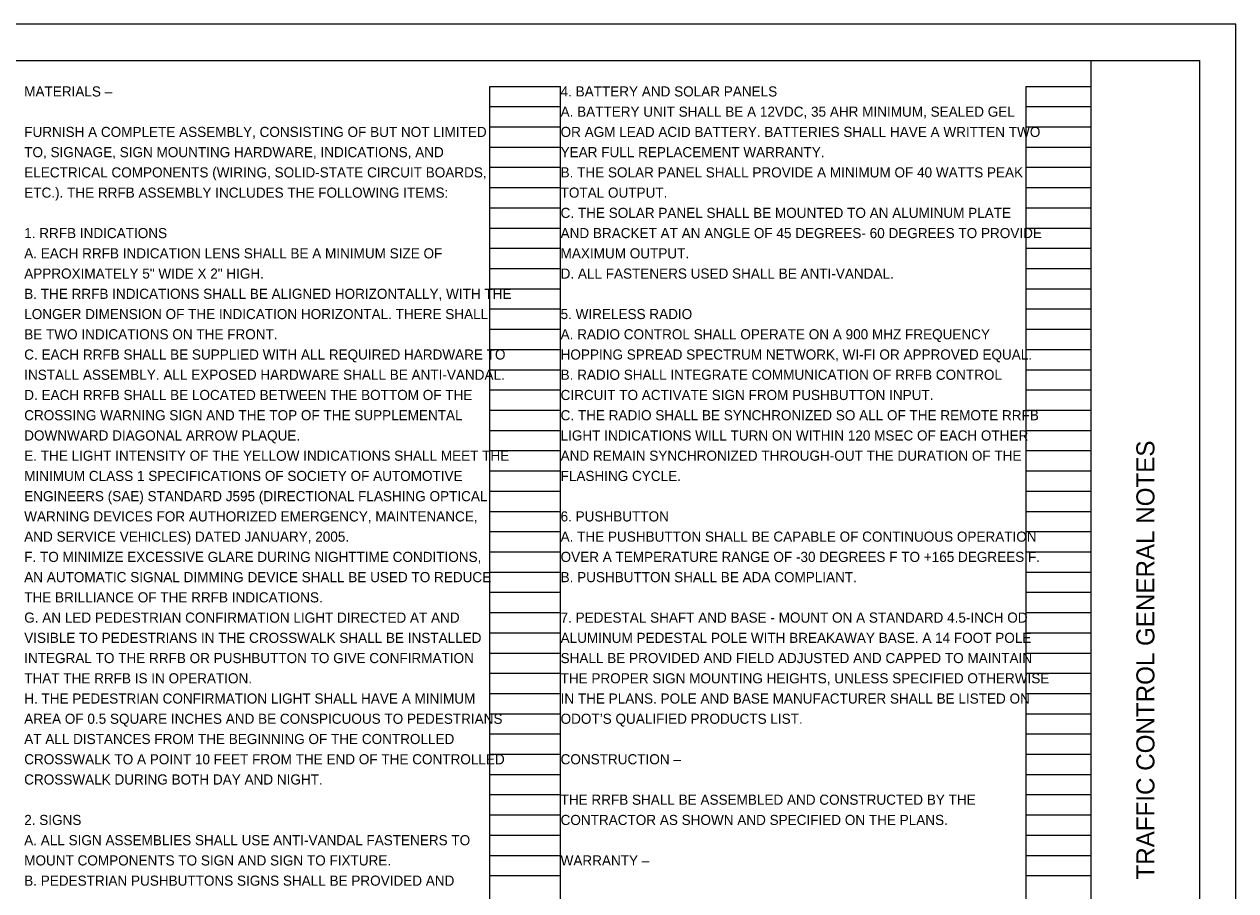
# Model space of a CAD drawing. Extents: x 0 to 34, y 0 to 22.
# Drawn here: x 17.24 to 34, y 10.01 to 22 of the extents above; entities that cross this region are included whole.
import ezdxf

# ---------------------------------------------------------------- set-up
doc = ezdxf.new("R2010")
doc.units = 0
for name, color, linetype in [('SH_Border', 7, 'Continuous'), ('SH_Cut_Line', 7, 'Continuous'), ('SH_Data', 7, 'Continuous'), ('SH_Text', 7, 'Continuous')]:
    doc.layers.add(name, color=color, linetype=linetype)

msp = doc.modelspace()

# ---------------------------------------------------------------- linework, layer by layer
at = {"layer": 'SH_Border'}
msp.add_line((32, 0.5), (32, 21.5), dxfattribs=at)
msp.add_lwpolyline([(1.5, 21.5), (33.5, 21.5), (33.5, 0.5), (1.5, 0.5)], close=True, dxfattribs=at)
at = {"layer": 'SH_Cut_Line'}
msp.add_lwpolyline([(0, 0), (34, 0), (34, 22), (0, 22)], close=True, dxfattribs=at)
at = {"layer": 'SH_Data'}
for p, q in [((23.68, 0.98), (23.68, 21.14)), ((23.68, 21.14), (24.66, 21.14)), ((24.66, 0.98), (24.66, 21.14)), ((31.1, 0.98), (31.1, 21.14)), ((31.1, 21.14), (32, 21.14)), ((32, 0.98), (32, 21.14)), ((23.68, 20.86), (24.66, 20.86)), ((31.1, 20.86), (32, 20.86)), ((23.68, 20.58), (24.66, 20.58)), ((31.1, 20.58), (32, 20.58)), ((23.68, 20.3), (24.66, 20.3)), ((31.1, 20.3), (32, 20.3)), ((23.68, 20.02), (24.66, 20.02)), ((31.1, 20.02), (32, 20.02)), ((23.68, 19.74), (24.66, 19.74)), ((31.1, 19.74), (32, 19.74)), ((23.68, 19.46), (24.66, 19.46)), ((31.1, 19.46), (32, 19.46)), ((23.68, 19.18), (24.66, 19.18)), ((31.1, 19.18), (32, 19.18)), ((23.68, 18.9), (24.66, 18.9)), ((31.1, 18.9), (32, 18.9)), ((23.68, 18.62), (24.66, 18.62)), ((31.1, 18.62), (32, 18.62)), ((23.68, 18.34), (24.66, 18.34)), ((31.1, 18.34), (32, 18.34)), ((23.68, 18.06), (24.66, 18.06)), ((31.1, 18.06), (32, 18.06)), ((23.68, 17.78), (24.66, 17.78)), ((31.1, 17.78), (32, 17.78)), ((23.68, 17.5), (24.66, 17.5)), ((31.1, 17.5), (32, 17.5)), ((23.68, 17.22), (24.66, 17.22)), ((31.1, 17.22), (32, 17.22)), ((23.68, 16.94), (24.66, 16.94)), ((31.1, 16.94), (32, 16.94)), ((23.68, 16.66), (24.66, 16.66)), ((31.1, 16.66), (32, 16.66)), ((23.68, 16.38), (24.66, 16.38)), ((31.1, 16.38), (32, 16.38)), ((23.68, 16.1), (24.66, 16.1)), ((31.1, 16.1), (32, 16.1)), ((23.68, 15.82), (24.66, 15.82)), ((31.1, 15.82), (32, 15.82)), ((23.68, 15.54), (24.66, 15.54)), ((31.1, 15.54), (32, 15.54)), ((23.68, 15.26), (24.66, 15.26)), ((31.1, 15.26), (32, 15.26)), ((23.68, 14.98), (24.66, 14.98)), ((31.1, 14.98), (32, 14.98)), ((23.68, 14.7), (24.66, 14.7)), ((31.1, 14.7), (32, 14.7)), ((23.68, 14.42), (24.66, 14.42)), ((31.1, 14.42), (32, 14.42)), ((23.68, 14.14), (24.66, 14.14)), ((31.1, 14.14), (32, 14.14)), ((23.68, 13.86), (24.66, 13.86)), ((31.1, 13.86), (32, 13.86)), ((23.68, 13.58), (24.66, 13.58)), ((31.1, 13.58), (32, 13.58)), ((23.68, 13.3), (24.66, 13.3)), ((31.1, 13.3), (32, 13.3)), ((23.68, 13.02), (24.66, 13.02)), ((31.1, 13.02), (32, 13.02)), ((23.68, 12.74), (24.66, 12.74)), ((31.1, 12.74), (32, 12.74)), ((23.68, 12.46), (24.66, 12.46)), ((31.1, 12.46), (32, 12.46)), ((23.68, 12.18), (24.66, 12.18)), ((31.1, 12.18), (32, 12.18)), ((23.68, 11.9), (24.66, 11.9)), ((31.1, 11.9), (32, 11.9)), ((23.68, 11.62), (24.66, 11.62)), ((31.1, 11.62), (32, 11.62)), ((23.68, 11.34), (24.66, 11.34)), ((31.1, 11.34), (32, 11.34)), ((23.68, 11.06), (24.66, 11.06)), ((31.1, 11.06), (32, 11.06)), ((23.68, 10.78), (24.66, 10.78)), ((31.1, 10.78), (32, 10.78)), ((23.68, 10.5), (24.66, 10.5)), ((31.1, 10.5), (32, 10.5)), ((23.68, 10.22), (24.66, 10.22)), ((31.1, 10.22), (32, 10.22))]:
    msp.add_line(p, q, dxfattribs=at)

# ---------------------------------------------------------------- texts
msp.add_text('TRAFFIC CONTROL GENERAL NOTES', height=0.25, rotation=90, dxfattribs=at).set_placement((32.875, 10.166))
at = {"layer": 'SH_Text'}
for s, p in [('MATERIALS –', (17.24, 21)), ('4. BATTERY AND SOLAR PANELS', (24.66, 21)), ('A. BATTERY UNIT SHALL BE A 12VDC, 35 AHR MINIMUM, SEALED GEL ', (24.66, 20.72)), ('FURNISH A COMPLETE ASSEMBLY, CONSISTING OF BUT NOT LIMITED ', (17.24, 20.44)), ('OR AGM LEAD ACID BATTERY. BATTERIES SHALL HAVE A WRITTEN TWO ', (24.66, 20.44)), ('TO, SIGNAGE, SIGN MOUNTING HARDWARE, INDICATIONS, AND ', (17.24, 20.16)), ('YEAR FULL REPLACEMENT WARRANTY.', (24.66, 20.16)), ('ELECTRICAL COMPONENTS (WIRING, SOLID-STATE CIRCUIT BOARDS, ', (17.24, 19.88)), ('B. THE SOLAR PANEL SHALL PROVIDE A MINIMUM OF 40 WATTS PEAK ', (24.66, 19.88)), ('ETC.). THE RRFB ASSEMBLY INCLUDES THE FOLLOWING ITEMS:', (17.24, 19.6)), ('TOTAL OUTPUT.', (24.66, 19.6)), ('C. THE SOLAR PANEL SHALL BE MOUNTED TO AN ALUMINUM PLATE ', (24.66, 19.32)), ('1. RRFB INDICATIONS', (17.24, 19.04)), ('AND BRACKET AT AN ANGLE OF 45 DEGREES- 60 DEGREES TO PROVIDE ', (24.66, 19.04)), ('A. EACH RRFB INDICATION LENS SHALL BE A MINIMUM SIZE OF ', (17.24, 18.76)), ('MAXIMUM OUTPUT.', (24.66, 18.76)), ('APPROXIMATELY 5" WIDE X 2" HIGH.', (17.24, 18.48)), ('D. ALL FASTENERS USED SHALL BE ANTI-VANDAL.', (24.66, 18.48)), ('B. THE RRFB INDICATIONS SHALL BE ALIGNED HORIZONTALLY, WITH THE ', (17.24, 18.2)), ('LONGER DIMENSION OF THE INDICATION HORIZONTAL. THERE SHALL ', (17.24, 17.92)), ('5. WIRELESS RADIO', (24.66, 17.92)), ('BE TWO INDICATIONS ON THE FRONT.', (17.24, 17.64)), ('A. RADIO CONTROL SHALL OPERATE ON A 900 MHZ FREQUENCY ', (24.66, 17.64)), ('C. EACH RRFB SHALL BE SUPPLIED WITH ALL REQUIRED HARDWARE TO ', (17.24, 17.36)), ('HOPPING SPREAD SPECTRUM NETWORK, WI-FI OR APPROVED EQUAL.', (24.66, 17.36)), ('INSTALL ASSEMBLY. ALL EXPOSED HARDWARE SHALL BE ANTI-VANDAL.', (17.24, 17.08)), ('B. RADIO SHALL INTEGRATE COMMUNICATION OF RRFB CONTROL ', (24.66, 17.08)), ('D. EACH RRFB SHALL BE LOCATED BETWEEN THE BOTTOM OF THE ', (17.24, 16.8)), ('CIRCUIT TO ACTIVATE SIGN FROM PUSHBUTTON INPUT.', (24.66, 16.8)), ('CROSSING WARNING SIGN AND THE TOP OF THE SUPPLEMENTAL ', (17.24, 16.52)), ('C. THE RADIO SHALL BE SYNCHRONIZED SO ALL OF THE REMOTE RRFB ', (24.66, 16.52)), ('DOWNWARD DIAGONAL ARROW PLAQUE.', (17.24, 16.24)), ('LIGHT INDICATIONS WILL TURN ON WITHIN 120 MSEC OF EACH OTHER ', (24.66, 16.24)), ('E. THE LIGHT INTENSITY OF THE YELLOW INDICATIONS SHALL MEET THE ', (17.24, 15.96)), ('AND REMAIN SYNCHRONIZED THROUGH-OUT THE DURATION OF THE ', (24.66, 15.96)), ('MINIMUM CLASS 1 SPECIFICATIONS OF SOCIETY OF AUTOMOTIVE ', (17.24, 15.68)), ('FLASHING CYCLE.', (24.66, 15.68)), ('ENGINEERS (SAE) STANDARD J595 (DIRECTIONAL FLASHING OPTICAL ', (17.24, 15.4)), ('WARNING DEVICES FOR AUTHORIZED EMERGENCY, MAINTENANCE, ', (17.24, 15.12)), ('6. PUSHBUTTON', (24.66, 15.12)), ('AND SERVICE VEHICLES) DATED JANUARY, 2005.', (17.24, 14.84)), ('A. THE PUSHBUTTON SHALL BE CAPABLE OF CONTINUOUS OPERATION ', (24.66, 14.84)), ('F. TO MINIMIZE EXCESSIVE GLARE DURING NIGHTTIME CONDITIONS, ', (17.24, 14.56)), ('OVER A TEMPERATURE RANGE OF -30 DEGREES F TO +165 DEGREES F.', (24.66, 14.56)), ('AN AUTOMATIC SIGNAL DIMMING DEVICE SHALL BE USED TO REDUCE ', (17.24, 14.28)), ('B. PUSHBUTTON SHALL BE ADA COMPLIANT.', (24.66, 14.28)), ('THE BRILLIANCE OF THE RRFB INDICATIONS.', (17.24, 14)), ('G. AN LED PEDESTRIAN CONFIRMATION LIGHT DIRECTED AT AND ', (17.24, 13.72)), ('7. PEDESTAL SHAFT AND BASE - MOUNT ON A STANDARD 4.5-INCH OD ', (24.66, 13.72)), ('VISIBLE TO PEDESTRIANS IN THE CROSSWALK SHALL BE INSTALLED ', (17.24, 13.44)), ('ALUMINUM PEDESTAL POLE WITH BREAKAWAY BASE. A 14 FOOT POLE ', (24.66, 13.44)), ('INTEGRAL TO THE RRFB OR PUSHBUTTON TO GIVE CONFIRMATION ', (17.24, 13.16)), ('SHALL BE PROVIDED AND FIELD ADJUSTED AND CAPPED TO MAINTAIN ', (24.66, 13.16)), ('THAT THE RRFB IS IN OPERATION.', (17.24, 12.88)), ('THE PROPER SIGN MOUNTING HEIGHTS, UNLESS SPECIFIED OTHERWISE ', (24.66, 12.88)), ('H. THE PEDESTRIAN CONFIRMATION LIGHT SHALL HAVE A MINIMUM ', (17.24, 12.6)), ('IN THE PLANS. POLE AND BASE MANUFACTURER SHALL BE LISTED ON ', (24.66, 12.6)), ('AREA OF 0.5 SQUARE INCHES AND BE CONSPICUOUS TO PEDESTRIANS ', (17.24, 12.32)), ('ODOT’S QUALIFIED PRODUCTS LIST.', (24.66, 12.32)), ('AT ALL DISTANCES FROM THE BEGINNING OF THE CONTROLLED ', (17.24, 12.04)), ('CROSSWALK TO A POINT 10 FEET FROM THE END OF THE CONTROLLED ', (17.24, 11.76)), ('CONSTRUCTION – ', (24.66, 11.76)), ('CROSSWALK DURING BOTH DAY AND NIGHT.', (17.24, 11.48)), ('THE RRFB SHALL BE ASSEMBLED AND CONSTRUCTED BY THE ', (24.66, 11.2)), ('2. SIGNS', (17.24, 10.92)), ('CONTRACTOR AS SHOWN AND SPECIFIED ON THE PLANS. ', (24.66, 10.92)), ('A. ALL SIGN ASSEMBLIES SHALL USE ANTI-VANDAL FASTENERS TO ', (17.24, 10.64)), ('MOUNT COMPONENTS TO SIGN AND SIGN TO FIXTURE.', (17.24, 10.36)), ('WARRANTY –', (24.66, 10.36)), ('B. PEDESTRIAN PUSHBUTTONS SIGNS SHALL BE PROVIDED AND ', (17.24, 10.08))]:
    msp.add_text(s, height=0.14, dxfattribs=at).set_placement(p)

doc.saveas('drawing.dxf')
